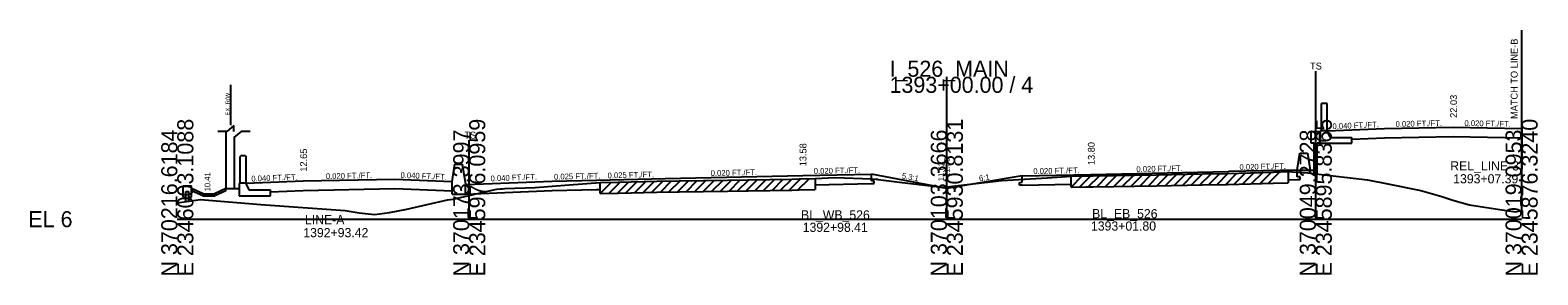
# Model space of a CAD drawing. Extents: x -170 to 2527928, y -10 to 1619750.
# Drawn here: x 1974.3 to 2237.6, y 5490.3 to 5532.9 of the extents above; entities that cross this region are included whole.
import ezdxf

# ---------------------------------------------------------------- set-up
doc = ezdxf.new("R2010")
doc.units = 0
for name, color, linetype in [('Default', 7, 'Continuous'), ('RD_GPK_XS_Cell', 7, 'Continuous'), ('RD_PD_NOISE-WALL-GM', 7, 'Continuous'), ('RD_PD_WallFill', 7, 'Continuous'), ('RD_XS_Base', 7, 'Continuous'), ('RD_XS_EarthShd', 7, 'Continuous'), ('RD_XS_ExGround', 7, 'Continuous'), ('RD_XS_ExPaveRet', 7, 'Continuous'), ('RD_XS_ExRW', 7, 'Continuous'), ('RD_XS_MatchLine', 7, 'Continuous'), ('RD_XS_Pave', 7, 'Continuous'), ('RD_XS_PaveShd', 7, 'Continuous'), ('RD_XS_TieSlope', 7, 'Continuous'), ('RD_XS_TX_Elev_EX', 7, 'Continuous'), ('RD_XS_TX_Elev_PR', 7, 'Continuous'), ('RD_XS_TX_Slope', 7, 'Continuous'), ('RD_XS_TX_Station', 7, 'Continuous')]:
    doc.layers.add(name, color=color, linetype=linetype)

msp = doc.modelspace()

# ---------------------------------------------------------------- linework, layer by layer
at = {"layer": 'Default'}
for p, q in [((2008.63, 5515.28), (2007.05, 5515.28)), ((2009.88, 5516.31), (2008.63, 5515.28)), ((2009.88, 5515.28), (2009.88, 5516.31)), ((2011.13, 5515.28), (2009.88, 5514.25)), ((2012.72, 5515.28), (2011.13, 5515.28))]:
    msp.add_line(p, q, dxfattribs=at)
at = {"layer": 'RD_GPK_XS_Cell'}
for p, q in [((2134.36, 5500), (2134.36, 5524.8)), ((2000, 5500), (2050.97, 5500)), ((2050.97, 5500), (2134.36, 5500)), ((2134.36, 5500), (2198.78, 5500)), ((2198.78, 5500), (2234.72, 5500))]:
    msp.add_line(p, q, dxfattribs=at)
at = {"layer": 'RD_PD_NOISE-WALL-GM'}
for p, q in [((2008.5, 5515.28), (2008.5, 5505.33)), ((2010, 5505.33), (2010, 5514.35)), ((2195.53, 5508.52), (2196.01, 5511.52)), ((2196.01, 5511.52), (2197.35, 5511.52)), ((2197.35, 5511.52), (2197.83, 5508.52)), ((2048, 5506.57), (2048.48, 5509.57)), ((2048.48, 5509.57), (2049.76, 5509.57)), ((2049.76, 5509.57), (2050.33, 5506.01)), ((2048, 5504.37), (2048, 5506.57)), ((2050.33, 5504.37), (2050.33, 5506.01)), ((2048, 5504.37), (2050.33, 5504.37))]:
    msp.add_line(p, q, dxfattribs=at)
at = {"layer": 'RD_PD_WallFill'}
for p, q in [((2199.78, 5515.39), (2199.78, 5520.14)), ((2200.78, 5520.14), (2199.78, 5520.14)), ((2200.78, 5515.39), (2200.78, 5520.14)), ((2199.5, 5515.22), (2198, 5515.22)), ((2198, 5513.22), (2198, 5515.22)), ((2199.65, 5515.39), (2199.49, 5515.22)), ((2199.5, 5513.22), (2199.5, 5515.22)), ((2199.57, 5515.22), (2199.5, 5515.22)), ((2199.57, 5515.3), (2199.57, 5513.22)), ((2200.78, 5515.39), (2199.65, 5515.39)), ((2200.78, 5515.39), (2200.78, 5515.22)), ((2200.78, 5515.22), (2201.27, 5514.22)), ((2234.78, 5515.79), (2234.72, 5501.5)), ((2198.5, 5513.22), (2198, 5513.22)), ((2198.5, 5507.91), (2198.5, 5513.22)), ((2199.5, 5513.22), (2199, 5513.22)), ((2199, 5507.86), (2199, 5513.22)), ((2199.5, 5513.22), (2205.07, 5513.22)), ((2199.57, 5513.22), (2199.5, 5513.22)), ((2201.27, 5514.22), (2205.07, 5514.22)), ((2205.07, 5513.22), (2205.07, 5514.22)), ((2011.08, 5511), (2011, 5510.92)), ((2011, 5506.25), (2011, 5510.92)), ((2011.92, 5511), (2011.08, 5511)), ((2011.92, 5511), (2012, 5510.92)), ((2012, 5506.25), (2012, 5510.92)), ((2195.53, 5508.52), (2198.5, 5508.52)), ((2001, 5505.83), (2002.5, 5505.83)), ((2001, 5503.83), (2001, 5505.83)), ((2001.5, 5503.04), (2001.5, 5504.83)), ((2001.5, 5504.83), (2002, 5504.83)), ((2002, 5503.11), (2002, 5504.83)), ((2002.5, 5503.83), (2002.5, 5505.83)), ((2004.5, 5504.41), (2002.5, 5505.33)), ((2004.43, 5504.08), (2002.5, 5504.96)), ((2008.5, 5505.33), (2006.5, 5504.41)), ((2008.5, 5504.96), (2006.57, 5504.08)), ((2008.5, 5504.96), (2008.5, 5505.33)), ((2010.87, 5506.25), (2010.79, 5506.17)), ((2010.79, 5506.17), (2010.79, 5504.08)), ((2012, 5506.25), (2010.87, 5506.25)), ((2012, 5506.25), (2012, 5506.08)), ((2012, 5506.08), (2012.49, 5505.08)), ((2012.49, 5505.08), (2016.29, 5505.08)), ((2016.29, 5504.08), (2016.29, 5505.08)), ((2001, 5503.83), (2001.5, 5503.83)), ((2002, 5503.83), (2002.5, 5503.83)), ((2004.43, 5504.08), (2006.57, 5504.08)), ((2004.5, 5504.41), (2006.5, 5504.41)), ((2010.79, 5504.08), (2016.29, 5504.08))]:
    msp.add_line(p, q, dxfattribs=at)
at = {"layer": 'RD_XS_Base'}
for p, q in [((2205.07, 5513.92), (2210.78, 5514.15)), ((2210.78, 5514.15), (2222.78, 5514.39)), ((2222.78, 5514.39), (2234.78, 5514.15)), ((2121.2, 5506.69), (2121.2, 5507.82)), ((2147.53, 5506.42), (2147.53, 5507.56)), ((2195.53, 5507.38), (2195.53, 5508.52)), ((2196.03, 5507.39), (2195.53, 5507.38)), ((2196.03, 5506.89), (2196.03, 5507.39)), ((2016.29, 5504.78), (2022, 5505.01)), ((2022, 5505.01), (2038, 5505.33)), ((2038, 5505.33), (2048, 5504.93)), ((2050.33, 5504.37), (2065.46, 5504.98)), ((2065.46, 5504.98), (2073.2, 5505.17)), ((2073.2, 5505.17), (2073.84, 5505.18)), ((2111.36, 5505.99), (2121.2, 5506.19)), ((2121.7, 5506.7), (2121.2, 5506.69)), ((2121.2, 5506.19), (2121.7, 5506.2)), ((2121.7, 5506.2), (2121.7, 5506.7)), ((2147.03, 5506.41), (2147.53, 5506.42)), ((2147.03, 5505.91), (2147.03, 5506.41)), ((2147.53, 5505.92), (2147.03, 5505.91)), ((2147.53, 5505.92), (2156.05, 5506.09)), ((2193.94, 5506.85), (2195.53, 5506.88)), ((2195.53, 5506.88), (2196.03, 5506.89))]:
    msp.add_line(p, q, dxfattribs=at)
at = {"layer": 'RD_XS_EarthShd'}
msp.add_line((2008.5, 5505.33), (2010.79, 5505.33), dxfattribs=at)
at = {"layer": 'RD_XS_ExGround'}
msp.add_lwpolyline([(2000, 5502.83), (2004.04, 5503.4), (2014.57, 5502.55), (2029.29, 5501.48), (2031.77, 5501.09), (2034.44, 5500.83), (2037.03, 5501.13), (2040.07, 5501.73), (2047.17, 5503.34), (2048.18, 5503.48), (2050.97, 5504.12), (2054.46, 5504.92), (2055.79, 5505.24), (2056.39, 5505.28), (2056.71, 5505.29), (2057.21, 5505.31), (2062.49, 5505.5), (2068.42, 5505.95), (2073.84, 5506.37), (2076.98, 5506.44), (2083.71, 5506.62), (2087.62, 5506.68), (2096.09, 5506.8), (2099.66, 5506.86), (2107.29, 5506.98), (2108.6, 5507.01), (2111.36, 5507.07), (2114.83, 5507.27), (2121.24, 5507), (2122.03, 5506.95), (2122.23, 5506.94), (2122.37, 5506.93), (2126.59, 5506.39), (2133.03, 5505.61), (2133.26, 5505.57), (2133.56, 5505.54), (2133.99, 5505.58), (2134.36, 5505.62), (2143.95, 5506.74), (2151.86, 5507.21), (2156.05, 5507.49), (2158.68, 5507.53), (2159.92, 5507.54), (2167.13, 5507.67), (2170.91, 5507.74), (2179.03, 5507.9), (2183.34, 5507.97), (2191.38, 5508.21), (2193.94, 5508.27), (2195.48, 5508.17), (2197.37, 5508.04), (2198.78, 5507.88), (2207.83, 5506.87), (2211.06, 5506.23), (2217.13, 5505.01), (2220.82, 5503.94), (2222.72, 5503.3), (2225.61, 5502.48), (2232.05, 5501.5), (2233.69, 5501.25), (2234.72, 5501.5)], dxfattribs=at)
at = {"layer": 'RD_XS_ExPaveRet'}
for p, q in [((2156.05, 5505.57), (2158, 5507.52)), ((2156.05, 5505.57), (2156.05, 5507.49)), ((2157.55, 5505.59), (2159.5, 5507.54)), ((2159.05, 5505.62), (2161, 5507.56)), ((2160.55, 5505.64), (2162.5, 5507.59)), ((2162.05, 5505.67), (2164, 5507.62)), ((2163.55, 5505.69), (2165.5, 5507.64)), ((2165.05, 5505.72), (2167, 5507.67)), ((2166.55, 5505.75), (2168.5, 5507.7)), ((2168.05, 5505.77), (2170, 5507.73)), ((2169.55, 5505.8), (2171.51, 5507.75)), ((2171.05, 5505.83), (2173.01, 5507.78)), ((2172.55, 5505.86), (2174.51, 5507.81)), ((2174.05, 5505.88), (2176.01, 5507.84)), ((2175.55, 5505.91), (2177.51, 5507.87)), ((2177.05, 5505.94), (2179.01, 5507.89)), ((2178.55, 5505.97), (2180.51, 5507.92)), ((2180.05, 5506), (2182.01, 5507.95)), ((2181.55, 5506.02), (2183.51, 5507.98)), ((2183.05, 5506.05), (2185.02, 5508.02)), ((2184.55, 5506.09), (2186.53, 5508.07)), ((2186.05, 5506.14), (2188.03, 5508.11)), ((2187.55, 5506.18), (2189.53, 5508.15)), ((2189.05, 5506.22), (2191.03, 5508.2)), ((2190.55, 5506.27), (2192.52, 5508.23)), ((2193.94, 5508.27), (2193.94, 5506.35)), ((2073.84, 5504.46), (2075.81, 5506.42)), ((2073.84, 5504.46), (2073.84, 5506.37)), ((2075.34, 5504.49), (2077.31, 5506.45)), ((2076.84, 5504.52), (2078.81, 5506.49)), ((2076.98, 5504.53), (2083.71, 5504.7)), ((2078.34, 5504.56), (2080.31, 5506.53)), ((2079.84, 5504.6), (2081.81, 5506.57)), ((2081.34, 5504.64), (2083.31, 5506.61)), ((2082.84, 5504.68), (2084.8, 5506.64)), ((2083.71, 5504.7), (2087.62, 5504.77)), ((2084.34, 5504.71), (2086.29, 5506.66)), ((2085.84, 5504.74), (2087.79, 5506.69)), ((2087.34, 5504.76), (2089.29, 5506.71)), ((2087.62, 5504.77), (2096.09, 5504.88)), ((2088.84, 5504.78), (2090.79, 5506.73)), ((2090.34, 5504.8), (2092.29, 5506.75)), ((2091.84, 5504.82), (2093.79, 5506.77)), ((2093.34, 5504.85), (2095.29, 5506.79)), ((2094.84, 5504.87), (2096.79, 5506.81)), ((2096.09, 5504.88), (2099.66, 5504.94)), ((2096.34, 5504.89), (2098.29, 5506.83)), ((2097.84, 5504.91), (2099.79, 5506.86)), ((2099.34, 5504.93), (2101.29, 5506.88)), ((2099.66, 5504.94), (2107.29, 5505.06)), ((2100.84, 5504.96), (2102.79, 5506.91)), ((2102.34, 5504.98), (2104.29, 5506.93)), ((2103.84, 5505.01), (2105.79, 5506.96)), ((2105.34, 5505.03), (2107.29, 5506.98)), ((2106.84, 5505.06), (2108.81, 5507.02)), ((2107.29, 5505.06), (2108.6, 5505.1)), ((2108.34, 5505.09), (2110.31, 5507.05)), ((2108.6, 5505.1), (2111.36, 5505.16)), ((2111.36, 5507.07), (2111.36, 5505.16)), ((2156.05, 5505.57), (2158.68, 5505.61)), ((2158.68, 5505.61), (2159.92, 5505.63)), ((2159.92, 5505.63), (2167.13, 5505.76)), ((2167.13, 5505.76), (2170.91, 5505.82)), ((2170.91, 5505.82), (2179.03, 5505.98)), ((2179.03, 5505.98), (2183.34, 5506.06)), ((2183.34, 5506.06), (2191.38, 5506.29)), ((2191.38, 5506.29), (2193.94, 5506.35)), ((2073.84, 5504.46), (2076.98, 5504.53))]:
    msp.add_line(p, q, dxfattribs=at)
at = {"layer": 'RD_XS_ExRW'}
msp.add_line((2009.36, 5516.38), (2009.36, 5523.38), dxfattribs=at)
at = {"layer": 'RD_XS_MatchLine'}
for p, q in [((2234.78, 5506.67), (2234.78, 5532.91)), ((2198.78, 5500), (2198.78, 5525.76)), ((2050.97, 5500), (2050.97, 5513.78))]:
    msp.add_line(p, q, dxfattribs=at)
at = {"layer": 'RD_XS_Pave'}
for p, q in [((2210.78, 5515.79), (2222.78, 5516.03)), ((2222.78, 5516.03), (2234.78, 5515.79)), ((2085.2, 5507.1), (2109.2, 5507.58)), ((2159.53, 5507.8), (2183.53, 5508.28)), ((2022, 5506.65), (2038, 5506.97)), ((2065.46, 5506.61), (2073.2, 5506.8)), ((2073.2, 5506.8), (2085.2, 5507.1))]:
    msp.add_line(p, q, dxfattribs=at)
at = {"layer": 'RD_XS_PaveShd'}
for p, q in [((2200.78, 5515.39), (2210.78, 5515.79)), ((2109.2, 5507.58), (2121.2, 5507.82)), ((2147.53, 5507.56), (2159.53, 5507.8)), ((2195.53, 5508.52), (2183.53, 5508.28)), ((2012, 5506.25), (2022, 5506.65)), ((2038, 5506.97), (2048, 5506.57)), ((2050.33, 5506.01), (2053.46, 5506.13)), ((2053.46, 5506.13), (2065.46, 5506.61))]:
    msp.add_line(p, q, dxfattribs=at)
at = {"layer": 'RD_XS_TieSlope'}
for p, q in [((2134.36, 5505.36), (2121.2, 5507.82)), ((2147.53, 5507.56), (2134.36, 5505.36))]:
    msp.add_line(p, q, dxfattribs=at)

# ---------------------------------------------------------------- texts
at = {"layer": 'RD_GPK_XS_Cell'}
for s, p in [('I_526_MAIN', (2124.36, 5524.8)), ('1393+00.00 / 4', (2124.36, 5522)), ('EL 6', (1974, 5498.6))]:
    msp.add_text(s, height=2.8, dxfattribs=at).set_placement(p)
for s, p in [('N 370216.6184', (2000, 5490)), ('E 2346003.1088', (2002.8, 5490)), ('N 370173.3997', (2050.97, 5490)), ('E 2345976.0959', (2053.77, 5490)), ('N 370103.3666', (2134.36, 5490)), ('E 2345930.8131', (2137.16, 5490)), ('N 370049.2728', (2198.78, 5490)), ('E 2345895.8365', (2201.58, 5490)), ('N 370019.0953', (2234.72, 5490)), ('E 2345876.3240', (2237.52, 5490))]:
    msp.add_text(s, height=2.8, rotation=90, dxfattribs=at).set_placement(p)
at = {"layer": 'RD_XS_ExRW'}
msp.add_text('EX. R/W ', height=0.75, rotation=90, dxfattribs=at).set_placement((2009.17, 5518.04))
at = {"layer": 'RD_XS_MatchLine'}
msp.add_text('MATCH TO LINE-B', height=1.2, rotation=90, dxfattribs=at).set_placement((2234.03, 5517.45))
for p in [(2197.79, 5526.07), (2050.11, 5514.03)]:
    msp.add_text('TS', height=1.2, dxfattribs=at).set_placement(p)
at = {"layer": 'RD_XS_TX_Elev_EX'}
msp.add_text('11.62', height=1, rotation=90, dxfattribs=at).set_placement((2133.86, 5506.62))
at = {"layer": 'RD_XS_TX_Elev_PR'}
msp.add_text('11.36', height=1, rotation=90, dxfattribs=at).set_placement((2134.86, 5507.36))
at = {"layer": 'RD_XS_TX_Slope'}
for s, rotation, p in [('0.040 FT./FT.', 2.2906, (2201.72, 5515.67)), ('0.020 FT./FT.', 1.1458, (2212.72, 5516.07)), ('0.020 FT./FT.', 358.8542, (2224.73, 5516.24)), ('10.41', 90, (2005.76, 5504.83)), ('0.040 FT./FT.', 2.2906, (2012.94, 5506.54)), ('0.020 FT./FT.', 1.1458, (2025.94, 5506.98)), ('0.040 FT./FT.', 357.7094, (2038.96, 5507.18)), ('0.040 FT./FT.', 2.2906, (2054.72, 5506.58)), ('0.025 FT./FT.', 1.4321, (2065.79, 5506.88)), ('0.025 FT./FT.', 1.4321, (2075.14, 5507.1)), ('0.020 FT./FT.', 1.1458, (2093.14, 5507.51)), ('0.020 FT./FT.', 1.1458, (2111.14, 5507.87)), ('5.3:1', 349.4055, (2126.44, 5507.1)), ('6:1', 9.4623, (2140.08, 5506.57)), ('0.020 FT./FT.', 1.1458, (2149.47, 5507.85)), ('0.020 FT./FT.', 1.1458, (2167.47, 5508.21)), ('0.020 FT./FT.', 1.1458, (2185.47, 5508.57))]:
    msp.add_text(s, height=1, rotation=rotation, dxfattribs=at).set_placement(p)
at = {"layer": 'RD_XS_TX_Station'}
for s, p in [(' 22.03', (2223.44, 5517.2)), (' 13.58', (2109.85, 5508.76)), (' 13.80', (2160.19, 5508.97)), (' 12.65', (2022.66, 5507.82))]:
    msp.add_text(s, height=1.2, rotation=90, dxfattribs=at).set_placement(p)
for s, p in [('REL_LINE-3', (2222.26, 5508.48)), ('1393+07.39', (2222.78, 5506.23)), ('LINE-A', (2022.29, 5499.1)), ('BL_WB_526', (2108.9, 5499.94)), ('1392+98.41', (2109.2, 5497.78)), ('1393+01.80', (2159.53, 5498)), ('BL_EB_526', (2159.73, 5500.15)), ('1392+93.42', (2022, 5496.85))]:
    msp.add_text(s, height=1.6, dxfattribs=at).set_placement(p)

doc.saveas('drawing.dxf')
